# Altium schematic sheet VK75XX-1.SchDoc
size A4
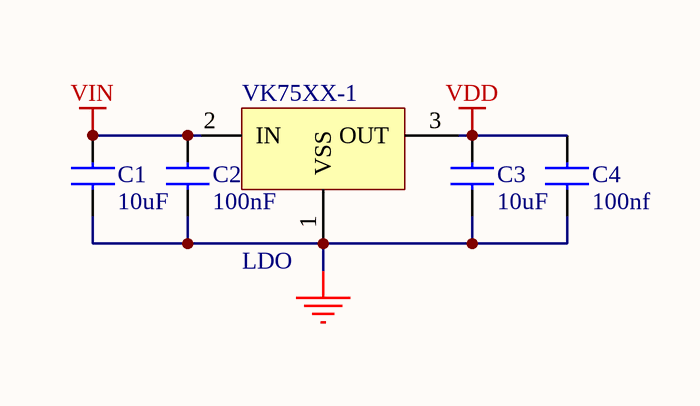
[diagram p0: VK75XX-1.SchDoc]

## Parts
C1  10uF  [1206C]
C2  100nF  [0603-C]
C3  value 10uF  [1206C]  (hidden comment: 100nF)
C4  value 100nf  [0603-C]  (hidden comment: 10uF)
VK75XX-1  LDO

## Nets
GND: C1.2 C2.2 C3.2 C4.2 VK75XX-1.1(VSS)
VDD: C3.1 C4.1 VK75XX-1.3(OUT)
VIN: C1.1 C2.1 VK75XX-1.2(IN)

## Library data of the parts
C1-C4 = CAP: Capacitor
